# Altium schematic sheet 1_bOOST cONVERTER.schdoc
size 254 x 203 mm; Symbol: Altium_A; Device: Altium_A; SheetNumber: 1; SheetTotal: 5
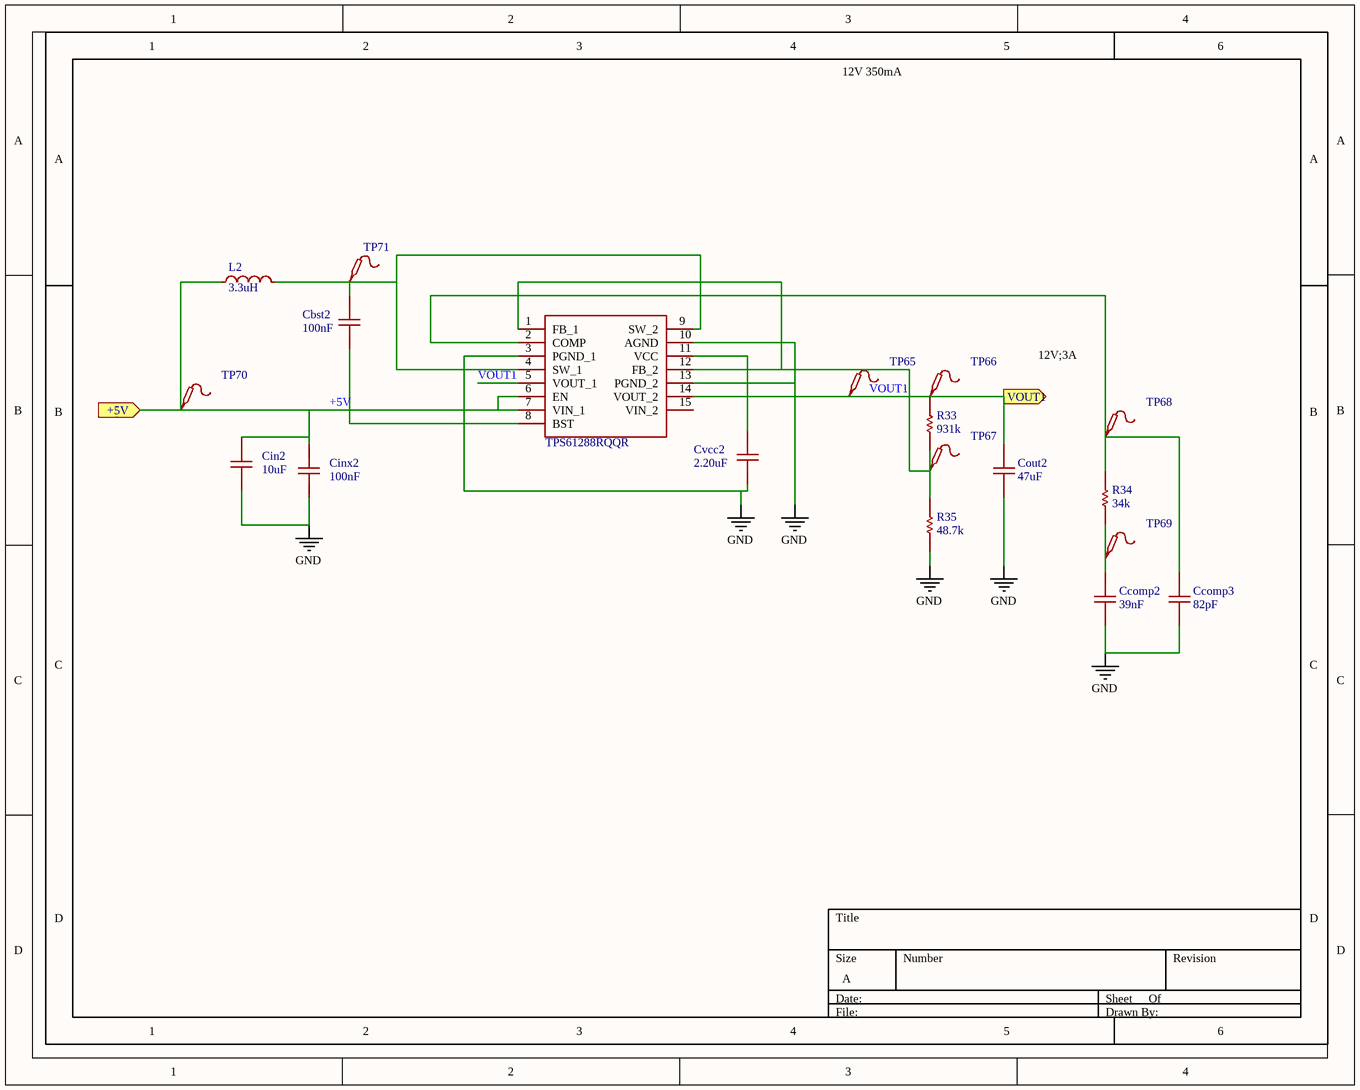
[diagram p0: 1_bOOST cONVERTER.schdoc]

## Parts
Cbst2  100nF  [C0201]  (value not drawn)
Ccomp2  39nF  [C0201]  (value not drawn)
Ccomp3  82pF  [C0201]  (value not drawn)
Cin2  10uF  [C0201]  (value not drawn)
Cinx2  100nF  [C0201]  (value not drawn)
Cout2  47uF  [C0201]  (value not drawn)
Cvcc2  2.20uF  [C0201]  (value not drawn)
L2  3.3uH  [L0402]  (value not drawn)
R33  value 931k  [R0805_NEW]  (hidden comment: MCR03..PFX1002)
R34  value 34k  [R0805_NEW]  (hidden comment: MCR03..PFX1002)
R35  value 48.7k  [R0805_NEW]  (hidden comment: MCR03..PFX1002)
TP65  Test-Point  [Test-Point-0.5mm]  (value not drawn)
TP66  Test-Point  [Test-Point-0.5mm]  (value not drawn)
TP67  Test-Point  [Test-Point-0.5mm]  (value not drawn)
TP68  Test-Point  [Test-Point-0.5mm]  (value not drawn)
TP69  Test-Point  [Test-Point-0.5mm]  (value not drawn)
TP70  Test-Point  [Test-Point-0.5mm]  (value not drawn)
TP71  Test-Point  [Test-Point-0.5mm]  (value not drawn)
U1  TPS61288RQQR  [TPS61288RQQR]  (value not drawn)

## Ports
+5V (in), VOUT1 (out)

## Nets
GND: Ccomp2.1 Ccomp3.1 Cin2.1 Cinx2.2 Cout2.1 Cvcc2.1 R35.2 U1.3(PGND_1) U1.10(AGND) U1.13(PGND_2)
+5V: Cin2.2 Cinx2.1 L2.2 TP70.1 U1.6(EN) U1.7(VIN_1) ; port +5V
VOUT1: Cout2.2 R33.2 TP65.1 TP66.1 U1.5(VOUT_1) U1.14(VOUT_2) ; port VOUT1
NetCbst2_1: Cbst2.1 L2.1 TP71.1 U1.4(SW_1) U1.9(SW_2)
NetCbst2_2: Cbst2.2 U1.8(BST)
NetCcomp2_2: Ccomp2.2 R34.1 TP69.1
NetCcomp3_2: Ccomp3.2 R34.2 TP68.1 U1.2(COMP)
NetCvcc2_2: Cvcc2.2 U1.11(VCC)
NetR33_1: R33.1 R35.1 TP67.1 U1.1(FB_1) U1.12(FB_2)

Not connected (* = marked no-connect by the designer): U1 15(VIN_2)

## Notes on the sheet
- 12V 350mA
- 12V;3A

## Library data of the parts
Cbst2 Ccomp2 Ccomp3 Cin2 Cinx2 Cout2 Cvcc2 = CAP_0201: Symbol: CAP; Convert to PCB: yes
L2 = L_0402: Symbol: 电感; Add into BOM: yes
R33-R35 = MCR03..PFX1002: Resistor; Symbol: Res1; Origin Footprint 2: AXIAL-0.3; Add into BOM: yes; Origin Footprint 1: RESC1608X55N
TP65-TP71 = Test-Point: Test Point 测试点; Add into BOM: yes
